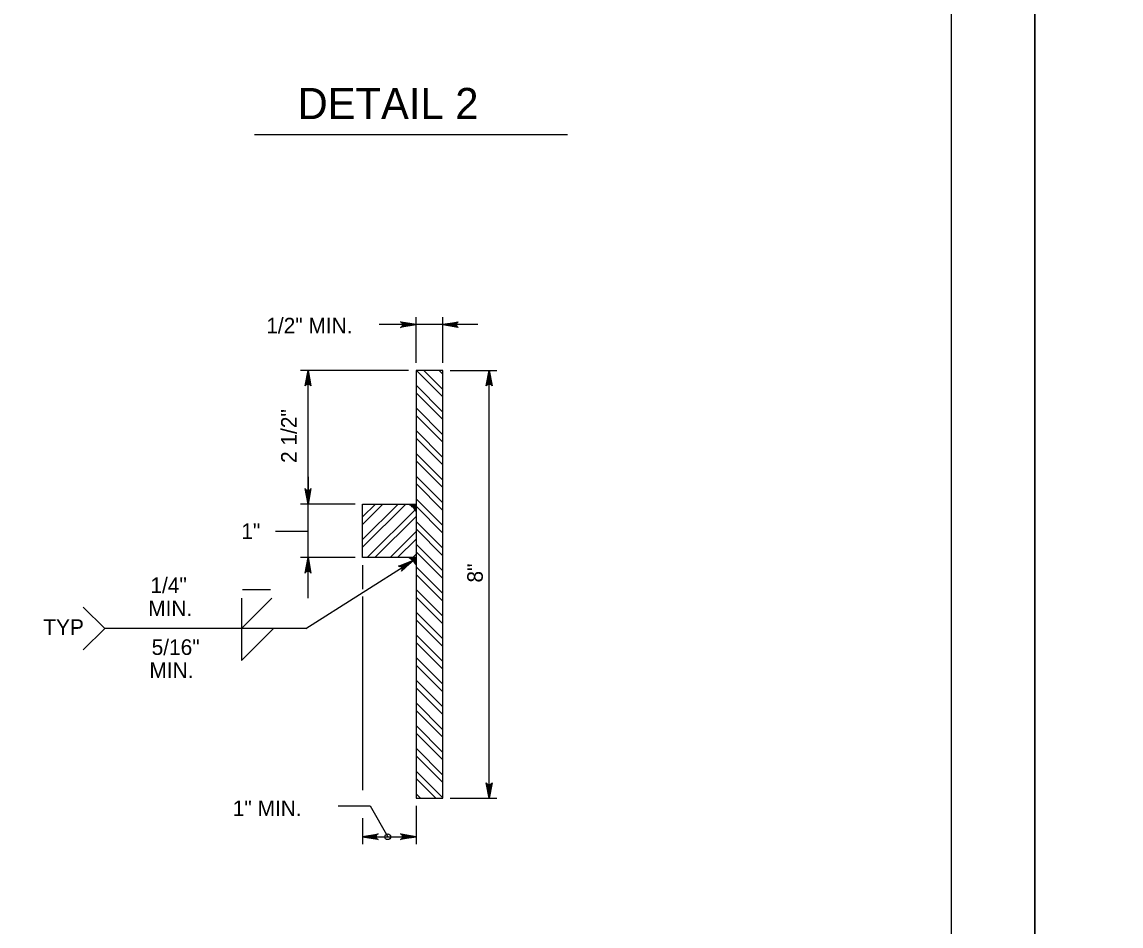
# Model space of a CAD drawing. Extents: x 2087776 to 2104538, y 970919 to 982612.
# Drawn here: x 2095414 to 2096108, y 975650 to 976220 of the extents above; entities that cross this region are included whole.
import ezdxf

# ---------------------------------------------------------------- set-up
doc = ezdxf.new("R2010")
doc.units = 0
doc.layers.add('1', color=7, linetype='Continuous')
doc.layers.add('PLT-BNDY', color=7, linetype='Continuous')

msp = doc.modelspace()

# ---------------------------------------------------------------- linework, layer by layer
at = {"layer": '1'}
for p, q in [((2095561.14, 976148.99), (2095758.48, 976148.99)), ((2095701.99, 976029.04), (2095639.77, 976029.04)), ((2095662.96, 976004.86), (2095662.96, 976033.77)), ((2095679.83, 976004.86), (2095679.83, 976033.77)), ((2095658.23, 976000.13), (2095590.1, 976000.13)), ((2095594.83, 975856.4), (2095594.83, 976000.13)), ((2095662.96, 976000.13), (2095662.96, 976000.13)), ((2095684.55, 976000.13), (2095713.8, 976000.13)), ((2095709.07, 975730.18), (2095709.07, 976000.13)), ((2095594.83, 975933.01), (2095594.83, 975915.78)), ((2095624.49, 975915.78), (2095590.1, 975915.78)), ((2095662.96, 975915.78), (2095662.96, 975915.78)), ((2095574.19, 975898.65), (2095594.83, 975898.65)), ((2095624.49, 975882.03), (2095590.1, 975882.03)), ((2095593.36, 975837.34), (2095661.12, 975880.26)), ((2095629.21, 975877.31), (2095629.21, 975862.1)), ((2095552.86, 975837.34), (2095571.89, 975856.36)), ((2095552.86, 975856.36), (2095552.86, 975837.34)), ((2095553.45, 975861.81), (2095571.04, 975861.81)), ((2095629.21, 975857.44), (2095629.21, 975735.23)), ((2095593.36, 975837.34), (2095466.55, 975837.34)), ((2095552.86, 975837.34), (2095552.86, 975817.09)), ((2095552.86, 975817.09), (2095573.11, 975837.34)), ((2095684.55, 975730.18), (2095713.8, 975730.18)), ((2095662.96, 975725.46), (2095662.96, 975701.21)), ((2095629.21, 975717.62), (2095629.21, 975701.21)), ((2095629.21, 975705.93), (2095662.96, 975705.93))]:
    msp.add_line(p, q, dxfattribs=at)
for points in [[(2096000.74, 974866.19), (2096000.74, 976716.58), (2093422, 976716.58), (2093422, 974866.19), (2096000.74, 974866.19), (2096000.74, 974952.67), (2095344.57, 974952.67), (2095344.57, 975164.86), (2096000.74, 975164.86), (2096000.74, 975259.89), (2095344.57, 975259.89), (2095344.57, 974866.19), (2095603.11, 974866.19), (2095603.11, 974952.67), (2095603.11, 974866.19), (2095855.73, 974866.19), (2095855.73, 974952.67), (2095855.73, 974912.26), (2096000.74, 974912.26)], [(2095662.96, 976029.04), (2095653.17, 976027.21), (2095653.55, 976027.47), (2095653.93, 976027.73), (2095654.12, 976028.06), (2095654.31, 976028.39), (2095654.37, 976028.72), (2095654.43, 976029.04), (2095654.37, 976029.37), (2095654.31, 976029.7), (2095654.12, 976030.03), (2095653.93, 976030.36), (2095653.55, 976030.62), (2095653.17, 976030.88), (2095662.96, 976029.04), (2095653.55, 976030.62), (2095653.93, 976030.36), (2095662.96, 976029.04), (2095654.12, 976030.03), (2095654.31, 976029.7), (2095662.96, 976029.04), (2095654.37, 976029.37), (2095654.43, 976029.04), (2095662.96, 976029.04), (2095654.37, 976028.72), (2095654.31, 976028.39), (2095662.96, 976029.04), (2095654.12, 976028.06), (2095653.93, 976027.73), (2095662.96, 976029.04), (2095653.55, 976027.47)], [(2095679.83, 976029.04), (2095689.61, 976030.88), (2095689.24, 976030.62), (2095688.86, 976030.36), (2095688.66, 976030.03), (2095688.47, 976029.7), (2095688.41, 976029.37), (2095688.36, 976029.04), (2095688.41, 976028.72), (2095688.47, 976028.39), (2095688.66, 976028.06), (2095688.86, 976027.73), (2095689.24, 976027.47), (2095689.61, 976027.21), (2095679.83, 976029.04), (2095689.24, 976027.47), (2095688.86, 976027.73), (2095679.83, 976029.04), (2095688.66, 976028.06), (2095688.47, 976028.39), (2095679.83, 976029.04), (2095688.41, 976028.72), (2095688.36, 976029.04), (2095679.83, 976029.04), (2095688.41, 976029.37), (2095688.47, 976029.7), (2095679.83, 976029.04), (2095688.66, 976030.03), (2095688.86, 976030.36), (2095679.83, 976029.04), (2095689.24, 976030.62)], [(2095594.83, 976000.13), (2095596.66, 975990.35), (2095596.4, 975990.73), (2095596.14, 975991.1), (2095595.81, 975991.3), (2095595.48, 975991.49), (2095595.15, 975991.55), (2095594.83, 975991.6), (2095594.5, 975991.55), (2095594.17, 975991.49), (2095593.84, 975991.3), (2095593.51, 975991.1), (2095593.25, 975990.73), (2095592.99, 975990.35), (2095594.83, 976000.13), (2095593.25, 975990.73), (2095593.51, 975991.1), (2095594.83, 976000.13), (2095593.84, 975991.3), (2095594.17, 975991.49), (2095594.83, 976000.13), (2095594.5, 975991.55), (2095594.83, 975991.6), (2095594.83, 976000.13), (2095595.15, 975991.55), (2095595.48, 975991.49), (2095594.83, 976000.13), (2095595.81, 975991.3), (2095596.14, 975991.1), (2095594.83, 976000.13), (2095596.4, 975990.73)], [(2095679.83, 975983.43), (2095663.13, 976000.13)], [(2095679.83, 975988.2), (2095667.9, 976000.13)], [(2095679.83, 975997.75), (2095677.44, 976000.13)], [(2095709.07, 976000.13), (2095710.91, 975990.35), (2095710.65, 975990.73), (2095710.38, 975991.1), (2095710.06, 975991.3), (2095709.73, 975991.49), (2095709.4, 975991.55), (2095709.07, 975991.6), (2095708.74, 975991.55), (2095708.42, 975991.49), (2095708.09, 975991.3), (2095707.76, 975991.1), (2095707.5, 975990.73), (2095707.24, 975990.35), (2095709.07, 976000.13), (2095707.5, 975990.73), (2095707.76, 975991.1), (2095709.07, 976000.13), (2095708.09, 975991.3), (2095708.42, 975991.49), (2095709.07, 976000.13), (2095708.74, 975991.55), (2095709.07, 975991.6), (2095709.07, 976000.13), (2095709.4, 975991.55), (2095709.73, 975991.49), (2095709.07, 976000.13), (2095710.06, 975991.3), (2095710.38, 975991.1), (2095709.07, 976000.13), (2095710.65, 975990.73)], [(2095679.83, 975973.89), (2095662.96, 975990.76)], [(2095679.83, 975969.12), (2095662.96, 975985.99)], [(2095679.83, 975959.58), (2095662.96, 975976.45)], [(2095679.83, 975954.8), (2095662.96, 975971.67)], [(2095679.83, 975945.26), (2095662.96, 975962.13)], [(2095679.83, 975940.48), (2095662.96, 975957.35)], [(2095679.83, 975930.93), (2095662.96, 975947.81)], [(2095679.83, 975926.17), (2095662.96, 975943.04)], [(2095679.83, 975916.62), (2095662.96, 975933.49)], [(2095594.83, 975915.78), (2095592.99, 975925.56), (2095593.25, 975925.19), (2095593.51, 975924.81), (2095593.84, 975924.61), (2095594.17, 975924.42), (2095594.5, 975924.36), (2095594.83, 975924.31), (2095595.15, 975924.36), (2095595.48, 975924.42), (2095595.81, 975924.61), (2095596.14, 975924.81), (2095596.4, 975925.19), (2095596.66, 975925.56), (2095594.83, 975915.78), (2095596.4, 975925.19), (2095596.14, 975924.81), (2095594.83, 975915.78), (2095595.81, 975924.61), (2095595.48, 975924.42), (2095594.83, 975915.78), (2095595.15, 975924.36), (2095594.83, 975924.31), (2095594.83, 975915.78), (2095594.5, 975924.36), (2095594.17, 975924.42), (2095594.83, 975915.78), (2095593.84, 975924.61), (2095593.51, 975924.81), (2095594.83, 975915.78), (2095593.25, 975925.19)], [(2095679.83, 975911.85), (2095662.96, 975928.72)], [(2095679.83, 975902.31), (2095662.96, 975919.18)], [(2095629.21, 975888.59), (2095656.4, 975915.78)], [(2095629.21, 975893.36), (2095651.63, 975915.78)], [(2095629.21, 975902.9), (2095642.08, 975915.78)], [(2095629.21, 975907.67), (2095637.31, 975915.78)], [(2095629.21, 975882.03), (2095629.21, 975915.78), (2095662.96, 975915.78), (2095662.96, 975882.03), (2095629.21, 975882.03)], [(2095632.2, 975882.03), (2095662.96, 975912.79)], [(2095658.55, 975915.56), (2095662.77, 975915.56), (2095662.77, 975911.34), (2095662.25, 975912), (2095661.99, 975912.48), (2095661.68, 975913.03), (2095661.21, 975913.62), (2095660.57, 975914.12), (2095659.98, 975914.68), (2095659.23, 975915.2), (2095658.63, 975915.61), (2095662.69, 975915.33), (2095659.77, 975915.04), (2095662.66, 975914.86), (2095660.36, 975914.5), (2095662.62, 975914.37), (2095660.98, 975914.01), (2095662.71, 975913.81), (2095661.53, 975913.44), (2095662.71, 975913.13), (2095661.89, 975912.79), (2095662.66, 975912.64), (2095662.15, 975912.41), (2095662.66, 975912.25), (2095662.43, 975912.02), (2095662.58, 975911.69), (2095662.56, 975915.43), (2095659.43, 975915.23), (2095661.09, 975914.17), (2095662.12, 975912.56), (2095662.27, 975915.25)], [(2095679.83, 975897.54), (2095662.96, 975914.41)], [(2095636.97, 975882.03), (2095662.96, 975908.01)], [(2095679.83, 975887.99), (2095662.96, 975904.86)], [(2095646.52, 975882.03), (2095662.96, 975898.47)], [(2095679.83, 975883.22), (2095662.96, 975900.09)], [(2095651.29, 975882.03), (2095662.96, 975893.7)], [(2095679.83, 975873.67), (2095662.96, 975890.55)], [(2095660.84, 975882.03), (2095662.96, 975884.15)], [(2095679.83, 975868.91), (2095662.96, 975885.77)], [(2095594.83, 975882.03), (2095596.66, 975872.24), (2095596.4, 975872.62), (2095596.14, 975873), (2095595.81, 975873.19), (2095595.48, 975873.39), (2095595.15, 975873.44), (2095594.83, 975873.5), (2095594.5, 975873.44), (2095594.17, 975873.39), (2095593.84, 975873.19), (2095593.51, 975873), (2095593.25, 975872.62), (2095592.99, 975872.24), (2095594.83, 975882.03), (2095593.25, 975872.62), (2095593.51, 975873), (2095594.83, 975882.03), (2095593.84, 975873.19), (2095594.17, 975873.39), (2095594.83, 975882.03), (2095594.5, 975873.44), (2095594.83, 975873.5), (2095594.83, 975882.03), (2095595.15, 975873.44), (2095595.48, 975873.39), (2095594.83, 975882.03), (2095595.81, 975873.19), (2095596.14, 975873), (2095594.83, 975882.03), (2095596.4, 975872.62)], [(2095661.12, 975880.26), (2095653.83, 975873.47), (2095654.01, 975873.89), (2095654.19, 975874.32), (2095654.18, 975874.7), (2095654.17, 975875.08), (2095654.04, 975875.38), (2095653.91, 975875.69), (2095653.69, 975875.94), (2095653.46, 975876.19), (2095653.12, 975876.36), (2095652.78, 975876.53), (2095652.33, 975876.55), (2095651.87, 975876.57), (2095661.12, 975880.26), (2095652.33, 975876.55), (2095652.78, 975876.53), (2095661.12, 975880.26), (2095653.12, 975876.36), (2095653.46, 975876.19), (2095661.12, 975880.26), (2095653.69, 975875.94), (2095653.91, 975875.69), (2095661.12, 975880.26), (2095654.04, 975875.38), (2095654.17, 975875.08), (2095661.12, 975880.26), (2095654.18, 975874.7), (2095654.19, 975874.32), (2095661.12, 975880.26), (2095654.01, 975873.89)], [(2095658.55, 975881.81), (2095662.77, 975881.81), (2095662.77, 975877.6), (2095662.25, 975878.25), (2095661.99, 975878.74), (2095661.68, 975879.29), (2095661.21, 975879.88), (2095660.57, 975880.37), (2095659.98, 975880.94), (2095659.23, 975881.46), (2095658.63, 975881.87), (2095662.69, 975881.58), (2095659.77, 975881.3), (2095662.66, 975881.12), (2095660.36, 975880.76), (2095662.62, 975880.63), (2095660.98, 975880.27), (2095662.71, 975880.06), (2095661.53, 975879.69), (2095662.71, 975879.39), (2095661.89, 975879.05), (2095662.66, 975878.9), (2095662.15, 975878.66), (2095662.66, 975878.51), (2095662.43, 975878.28), (2095662.58, 975877.94), (2095662.56, 975881.69), (2095659.43, 975881.48), (2095661.09, 975880.42), (2095662.12, 975878.82), (2095662.27, 975881.51)], [(2095679.83, 975859.36), (2095662.96, 975876.23)], [(2095679.83, 975854.58), (2095662.96, 975871.46)], [(2095679.83, 975845.04), (2095662.96, 975861.91)], [(2095679.83, 975840.27), (2095662.96, 975857.14)], [(2095453.05, 975850.84), (2095466.55, 975837.34), (2095453.05, 975823.84)], [(2095679.83, 975830.72), (2095662.96, 975847.59)], [(2095679.83, 975825.95), (2095662.96, 975842.82)], [(2095679.83, 975816.41), (2095662.96, 975833.28)], [(2095679.83, 975811.64), (2095662.96, 975828.51)], [(2095679.83, 975802.09), (2095662.96, 975818.97)], [(2095679.83, 975797.32), (2095662.96, 975814.2)], [(2095679.83, 975787.78), (2095662.96, 975804.65)], [(2095679.83, 975783), (2095662.96, 975799.88)], [(2095679.83, 975773.46), (2095662.96, 975790.33)], [(2095679.83, 975768.69), (2095662.96, 975785.56)], [(2095679.83, 975759.14), (2095662.96, 975776.01)], [(2095679.83, 975754.37), (2095662.96, 975771.24)], [(2095679.83, 975744.83), (2095662.96, 975761.7)], [(2095679.83, 975740.06), (2095662.96, 975756.93)], [(2095679.83, 975730.51), (2095662.96, 975747.38)], [(2095675.38, 975730.18), (2095662.96, 975742.61)], [(2095709.07, 975730.18), (2095707.24, 975739.97), (2095707.5, 975739.59), (2095707.76, 975739.21), (2095708.09, 975739.02), (2095708.42, 975738.82), (2095708.74, 975738.77), (2095709.07, 975738.71), (2095709.4, 975738.77), (2095709.73, 975738.82), (2095710.06, 975739.02), (2095710.38, 975739.21), (2095710.65, 975739.59), (2095710.91, 975739.97), (2095709.07, 975730.18), (2095710.65, 975739.59), (2095710.38, 975739.21), (2095709.07, 975730.18), (2095710.06, 975739.02), (2095709.73, 975738.82), (2095709.07, 975730.18), (2095709.4, 975738.77), (2095709.07, 975738.71), (2095709.07, 975730.18), (2095708.74, 975738.77), (2095708.42, 975738.82), (2095709.07, 975730.18), (2095708.09, 975739.02), (2095707.76, 975739.21), (2095709.07, 975730.18), (2095707.5, 975739.59)], [(2095665.84, 975730.18), (2095662.96, 975733.07)], [(2095613.74, 975725.5), (2095634.09, 975725.5), (2095645.04, 975705.93)], [(2095629.21, 975705.93), (2095639, 975707.77), (2095638.62, 975707.51), (2095638.24, 975707.25), (2095638.05, 975706.92), (2095637.85, 975706.59), (2095637.8, 975706.26), (2095637.74, 975705.93), (2095637.8, 975705.61), (2095637.85, 975705.28), (2095638.05, 975704.95), (2095638.24, 975704.62), (2095638.62, 975704.36), (2095639, 975704.1), (2095629.21, 975705.93), (2095638.62, 975704.36), (2095638.24, 975704.62), (2095629.21, 975705.93), (2095638.05, 975704.95), (2095637.85, 975705.28), (2095629.21, 975705.93), (2095637.8, 975705.61), (2095637.74, 975705.93), (2095629.21, 975705.93), (2095637.8, 975706.26), (2095637.85, 975706.59), (2095629.21, 975705.93), (2095638.05, 975706.92), (2095638.24, 975707.25), (2095629.21, 975705.93), (2095638.62, 975707.51)], [(2095662.96, 975705.93), (2095653.17, 975704.1), (2095653.55, 975704.36), (2095653.93, 975704.62), (2095654.12, 975704.95), (2095654.31, 975705.28), (2095654.37, 975705.61), (2095654.43, 975705.93), (2095654.37, 975706.26), (2095654.31, 975706.59), (2095654.12, 975706.92), (2095653.93, 975707.25), (2095653.55, 975707.51), (2095653.17, 975707.77), (2095662.96, 975705.93), (2095653.55, 975707.51), (2095653.93, 975707.25), (2095662.96, 975705.93), (2095654.12, 975706.92), (2095654.31, 975706.59), (2095662.96, 975705.93), (2095654.37, 975706.26), (2095654.43, 975705.93), (2095662.96, 975705.93), (2095654.37, 975705.61), (2095654.31, 975705.28), (2095662.96, 975705.93), (2095654.12, 975704.95), (2095653.93, 975704.62), (2095662.96, 975705.93), (2095653.55, 975704.36)]]:
    msp.add_lwpolyline(points, dxfattribs=at)
msp.add_lwpolyline([(2095662.96, 976000.13), (2095662.96, 975730.18), (2095679.83, 975730.18), (2095679.83, 976000.13)], close=True, dxfattribs=at)
msp.add_circle((2095645.05, 975705.93), 1.82, dxfattribs=at)
at = {"layer": 'PLT-BNDY'}
for points in [[(2093294.05, 976765.79), (2096053.23, 976765.79), (2096053.23, 974816.97), (2093294.05, 974816.97)], [(2096053.23, 976765.79), (2098812.42, 976765.79), (2098812.42, 974816.97), (2096053.23, 974816.97)]]:
    msp.add_lwpolyline(points, close=True, dxfattribs=at)

# ---------------------------------------------------------------- texts
at = {"layer": '1'}
for s, height, p in [('DETAIL 2', 19.685, (2095588.21, 976158.69)), ('1/2" MIN.', 9.843, (2095568.46, 976023.49)), ('1"', 9.843, (2095552.7, 975893.77)), ('1/4"', 9.843, (2095495.39, 975859.67)), ('MIN.', 9.843, (2095494, 975845.11)), ('TYP', 9.843, (2095427.81, 975833.26)), ('5/16"', 9.843, (2095496.16, 975820.62)), ('MIN.', 9.843, (2095494.76, 975806.06)), ('1" MIN.', 9.843, (2095547.34, 975718.92))]:
    msp.add_text(s, height=height, dxfattribs=at).set_placement(p)
for s, p in [('2 1/2"', (2095587.65, 975941.76)), ('8"', (2095705.07, 975866.31))]:
    msp.add_text(s, height=9.843, rotation=90, dxfattribs=at).set_placement(p)

doc.saveas('drawing.dxf')
